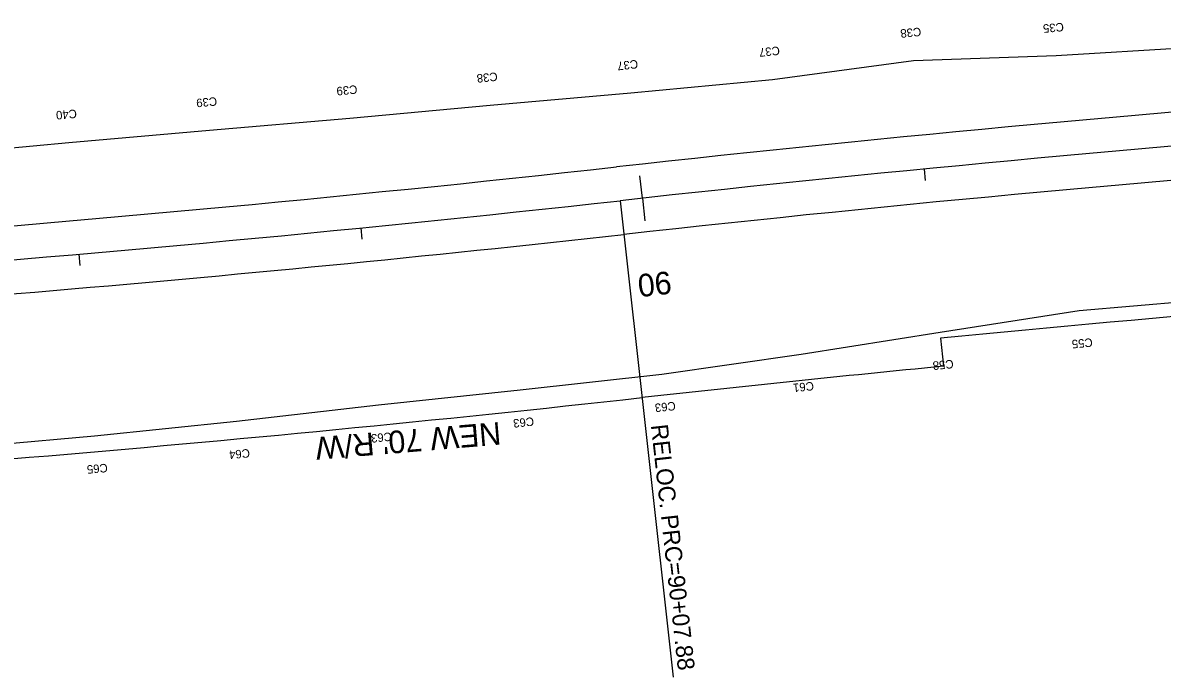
# Model space of a CAD drawing. Extents: x 1475170 to 1480100, y 1103245 to 1119475.
# Drawn here: x 1477623.9 to 1478026.2, y 1111188.1 to 1111419.2 of the extents above; entities that cross this region are included whole.
import ezdxf

# ---------------------------------------------------------------- set-up
doc = ezdxf.new("R2010")
doc.units = 0
for name, color, linetype in [('RD_HC_CL_Rel', 7, 'Continuous'), ('RD_HC_Data_Rel', 7, 'Continuous'), ('RD_HC_Data_Tic_Rel', 7, 'Continuous'), ('RD_HC_TX_Rel_Sta50', 7, 'Continuous'), ('RD_PD_CstnLmt', 7, 'Continuous'), ('RD_PD_CstnLmt_TX', 7, 'Continuous'), ('RD_PD_Final_TrvlWay', 7, 'Continuous'), ('RD_PD_RW', 7, 'Continuous'), ('RD_PD_RW_TX', 7, 'Continuous')]:
    doc.layers.add(name, color=color, linetype=linetype)

msp = doc.modelspace()

# ---------------------------------------------------------------- linework, layer by layer
at = {"layer": 'RD_HC_CL_Rel'}
for centre, start, end in [((1478732.36, 1103255.97), 92.160003, 96.322689), ((1476937.28, 1119456.82), 272.160003, 276.322689)]:
    msp.add_arc(centre, 8150, start, end, dxfattribs=at)
at = {"layer": 'RD_HC_Data_Rel'}
msp.add_line((1477834.82, 1111356.39), (1477853.47, 1111188.05), dxfattribs=at)
at = {"layer": 'RD_HC_Data_Tic_Rel'}
for p, q in [((1477942.12, 1111367.57), (1477942.51, 1111363.58)), ((1477842.66, 1111357.26), (1477841.78, 1111365.21)), ((1477842.66, 1111357.26), (1477843.53, 1111349.31)), ((1477743.21, 1111346.77), (1477743.6, 1111342.79)), ((1477643.64, 1111337.49), (1477643.99, 1111333.5))]:
    msp.add_line(p, q, dxfattribs=at)
at = {"layer": 'RD_PD_CstnLmt'}
for p, q in [((1477988.68, 1111407.51), (1477938.4, 1111405.79)), ((1478038.82, 1111410.65), (1477988.68, 1111407.51)), ((1477938.4, 1111405.79), (1477888.59, 1111399.12)), ((1477888.59, 1111399.12), (1477838.58, 1111394.37)), ((1477838.58, 1111394.37), (1477788.93, 1111389.96)), ((1477788.93, 1111389.96), (1477739.37, 1111385.43)), ((1477739.37, 1111385.43), (1477689.78, 1111381.23)), ((1477689.78, 1111381.23), (1477640.21, 1111376.88)), ((1477640.21, 1111376.88), (1477590.68, 1111372.12)), ((1478046.37, 1111321.78), (1477996.9, 1111317.46)), ((1477996.9, 1111317.46), (1477947.75, 1111309.84)), ((1477947.75, 1111309.84), (1477898.64, 1111302.06)), ((1477898.64, 1111302.06), (1477849.5, 1111294.97)), ((1477849.5, 1111294.97), (1477799.53, 1111289.49)), ((1477799.53, 1111289.49), (1477749.43, 1111284.19)), ((1477749.43, 1111284.19), (1477699.37, 1111278.35)), ((1477699.37, 1111278.35), (1477649.24, 1111273.17)), ((1477649.24, 1111273.17), (1477599.03, 1111268.8))]:
    msp.add_line(p, q, dxfattribs=at)
at = {"layer": 'RD_PD_Final_TrvlWay'}
for centre, radius, start, end in [((1478732.36, 1103255.97), 8162, 92.160003, 96.322689), ((1478732.36, 1103255.97), 8138, 92.160003, 96.322689), ((1476937.28, 1119456.82), 8138, 272.160003, 276.322689), ((1476937.28, 1119456.82), 8162, 273.388369, 276.322689)]:
    msp.add_arc(centre, radius, start, end, dxfattribs=at)
at = {"layer": 'RD_PD_RW'}
msp.add_line((1477947.94, 1111307.85), (1477948.91, 1111297.9), dxfattribs=at)
for centre, radius, start, end in [((1478732.36, 1103255.97), 8090, 92.160003, 95.564264), ((1478732.36, 1103255.97), 8080, 95.564264, 96.322689), ((1476937.28, 1119456.82), 8220, 273.291963, 276.322689)]:
    msp.add_arc(centre, radius, start, end, dxfattribs=at)

# ---------------------------------------------------------------- texts
at = {"layer": 'RD_HC_Data_Rel'}
msp.add_text('RELOC. PRC=90+07.88', height=6, rotation=276.3227, dxfattribs=at).set_placement((1477845.62, 1111277.1))
at = {"layer": 'RD_HC_TX_Rel_Sta50'}
msp.add_text('90', height=8, rotation=186.2673, dxfattribs=at).set_placement((1477852.46, 1111331.55))
at = {"layer": 'RD_PD_CstnLmt_TX'}
for s, rotation, p in [('C38', 185.5643, (1477940.92, 1111417.59)), ('C35', 185.2128, (1477991.28, 1111419.3)), ('C37', 185.9158, (1477891, 1111410.93)), ('C37', 186.2673, (1477840.93, 1111406.19)), ('C38', 186.0266, (1477791.35, 1111401.78)), ('C39', 185.6751, (1477741.86, 1111397.23)), ('C39', 185.3236, (1477692.35, 1111393.02)), ('C40', 184.9721, (1477642.85, 1111388.65)), ('C55', 185.2128, (1478001.45, 1111307.84)), ('C58', 185.5643, (1477952.35, 1111300.25)), ('C61', 185.9158, (1477903.02, 1111292.46)), ('C63', 186.2673, (1477854.22, 1111285.43)), ('C63', 186.0266, (1477804.21, 1111279.93)), ('C63', 185.6751, (1477754.05, 1111274.6)), ('C64', 185.3236, (1477703.93, 1111268.73)), ('C65', 184.9721, (1477653.74, 1111263.53))]:
    msp.add_text(s, height=3, rotation=rotation, dxfattribs=at).set_placement(p)
at = {"layer": 'RD_PD_RW_TX'}
msp.add_text("NEW 70' R/W", height=8, rotation=184.7578, dxfattribs=at).set_placement((1477792.36, 1111278.25))

doc.saveas('drawing.dxf')
